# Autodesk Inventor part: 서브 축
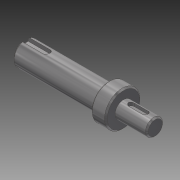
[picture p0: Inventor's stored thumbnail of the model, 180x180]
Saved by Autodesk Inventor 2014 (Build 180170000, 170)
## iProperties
Created: 2016-04
Part Number: 서브 축
Document SubType Name: Modeling
Designer: mdu
Density: 7.86 g/cm^3
Mass: 158.821 g
Surface Area: 57.924 cm^2
Volume: 20.2063 cm^3
Material: 강철, 연강
Appearance: 반광택
Author: mdu
Revision Number: 1
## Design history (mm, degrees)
sketch "스케치1"
  geometry: L1 (-16.331, 0)-(-108.831, 0); L2 (-16.331, 0)-(-16.331, -6); L3 (-16.331, -6)-(-38.831, -6); L4 (-38.831, -12)-(-46.5, -12); L5 (-46.5, -8.5)-(-108.831, -8.5); L6 (-108.831, -8.5)-(-108.831, 0); L7 (-46.5, -8.5)-(-46.5, -12); L8 (-38.831, -6)-(-38.831, -12); L9 (-46.5, 12.249)-(-46.5, -12.249) reference; L10 (-38.831, -17)-(-38.831, 17) reference; 2 further points
  constraints: 17 end point, 4 perpendicular, 2 collinear, 2 parallel, 1 horizontal, 1 midpoint, 1 point on line
  dimensions: "d1" = 12 diameter of L3 L1; "d2" = 24 diameter of L4 L1; "d3" = 17 diameter of L5 L1; "d18" = 22.5 distance of L2.end L3.end; "d20" = 70 distance between parallel lines of L6 L8; "d21" = 7.66872 distance of L4.start L4.end (derived)
revolve "회전1" sketch "스케치1" stored, may be unused: angle "d5" = 90 deg
feature "면 이동1"
chamfer "모따기1" distance "d6" = 0.5; stored, may be unused: second distance "d7" = 2, angle "d8" = 45 deg
node "작업 평면1"
sketch "스케치2"
  geometry: L1 (11.25, 5.5)-(11.25, -5.5) reference; L2 (-5.75, -2)-(4.25, -2); L3 (4.25, 2)-(-5.75, 2); A1 r 2 centre (4.25, 0) between (4.25, -2) and (4.25, 2); A2 r 2 centre (-5.75, 0) between (-5.75, 2) and (-5.75, -2); 2 further points
  constraints: 4 end point, 4 point on circle, 4 tangent, 2 centre point, 1 horizontal alignment, 1 midpoint, 1 parallel, 1 perpendicular
  dimensions: "d9" = 4 distance between parallel lines of L2 L3; "d10" = 14 dimension on A1 A2; "d11" = 5 distance edge to line of A1 L1
extrude "돌출1" cut sketch "스케치2" distance "d12" = 2.5; taper "d13" = 0 deg
node "작업 평면2"
sketch "스케치3"
  geometry: L1 (-31.166, -8)-(-31.166, 8) reference; L2 (-31.166, 2.5)-(-15.666, 2.5); L3 (-15.666, -2.5)-(-31.166, -2.5); A1 r 2.5 centre (-15.666, 0) between (-15.666, -2.5) and (-15.666, 2.5); 2 further points
  constraints: 4 end point, 2 perpendicular, 2 point on circle, 2 point on line, 2 tangent, 1 centre point, 1 horizontal alignment, 1 midpoint
  dimensions: "d14" = 5 distance between parallel lines of L3 L2; "d15" = 18 dimension on A1 L1
extrude "돌출2" cut sketch "스케치3" distance "d16" = 3; taper "d17" = 0 deg
node "솔리드1"
node "참조4"
node "참조5"
